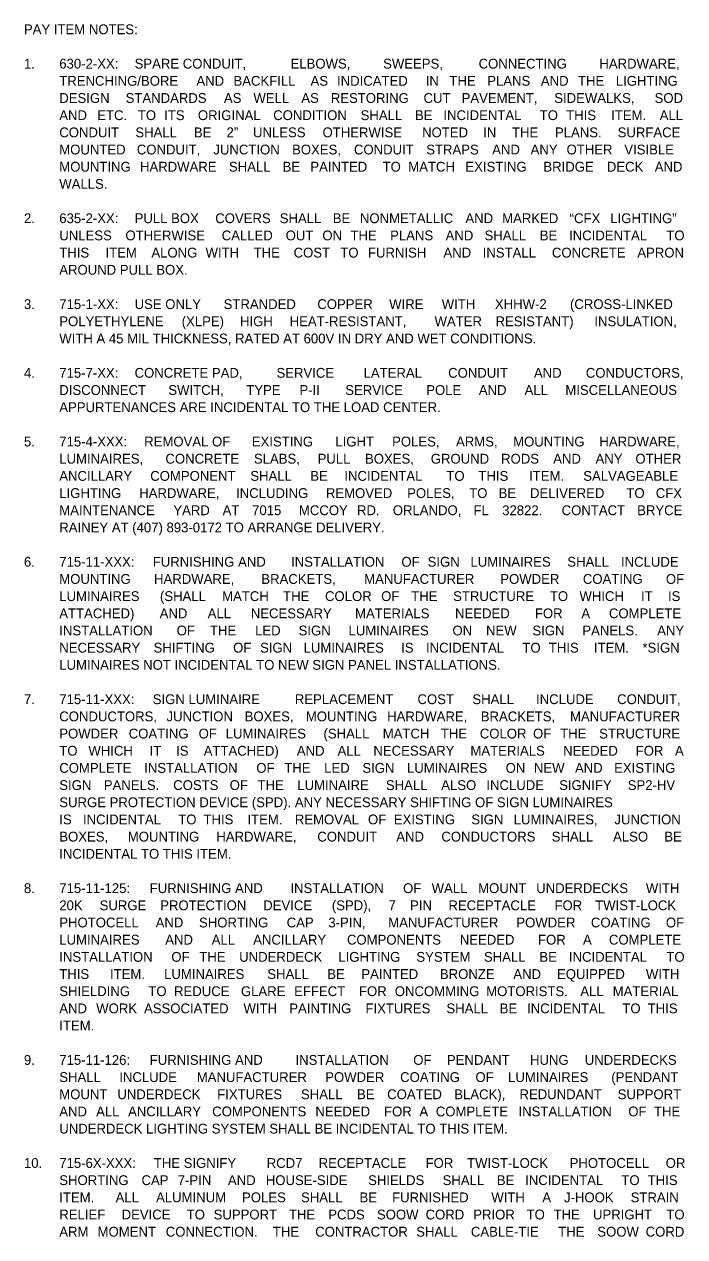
# Model space of a CAD drawing. Extents: x -55 to 2471539, y -90 to 3608906.
# Drawn here: x 27 to 498, y 2532 to 3397 of the extents above; entities that cross this region are included whole.
import ezdxf

# ---------------------------------------------------------------- set-up
doc = ezdxf.new("R2010")
doc.units = 0
doc.layers.add('XSCell', color=7, linetype='Continuous')

msp = doc.modelspace()

# ---------------------------------------------------------------- texts
at = {"layer": 'XSCell'}
for s, p in [('PAY ITEM NOTES:', (26.68, 3389.74)), ('630-2-XX:', (51.88, 3365.24)), (' SPARE CONDUIT, ', (103, 3365.24)), ('ELBOWS, ', (216.8, 3365.24)), ('SWEEPS, ', (282.82, 3365.24)), ('CONNECTING ', (350.92, 3365.24)), ('1.', (26.68, 3365.24)), ('HARDWARE, ', (437.06, 3365.24)), ('TRENCHING/BORE ', (51.88, 3352.99)), ('AND ', (149.66, 3352.99)), ('BACKFILL ', (176.11, 3352.99)), ('AS ', (231.06, 3352.99)), ('INDICATED ', (249.96, 3352.99)), ('IN ', (313.22, 3352.99)), ('THE ', (330.09, 3352.99)), ('PLANS ', (357.07, 3352.99)), ('AND ', (395.32, 3352.99)), ('THE ', (421.77, 3352.99)), ('LIGHTING ', (448.75, 3352.99)), ('DESIGN ', (51.88, 3340.74)), ('STANDARDS ', (99.2, 3340.74)), ('AS ', (169.29, 3340.74)), ('WELL ', (190.33, 3340.74)), ('AS ', (224.46, 3340.74)), ('RESTORING ', (245.49, 3340.74)), ('CUT ', (311.63, 3340.74)), ('PAVEMENT, ', (338.81, 3340.74)), ('SIDEWALKS, ', (404.84, 3340.74)), ('SOD ', (476.42, 3340.74)), ('AND ', (51.88, 3328.49)), ('ETC. ', (78.98, 3328.49)), ('TO ', (107.88, 3328.49)), ('ITS ', (126.69, 3328.49)), ('ORIGINAL ', (150.74, 3328.49)), ('CONDITION ', (204.43, 3328.49)), ('SHALL ', (266.79, 3328.49)), ('BE ', (305.52, 3328.49)), ('INCIDENTAL ', (325.8, 3328.49)), ('TO ', (394.52, 3328.49)), ('THIS ', (413.34, 3328.49)), ('ITEM. ', (445.46, 3328.49)), ('ALL ', (480.05, 3328.49)), ('CONDUIT ', (51.88, 3316.24)), ('SHALL ', (106.12, 3316.24)), ('BE ', (147.86, 3316.24)), ('2” ', (171.15, 3316.24)), ('UNLESS ', (190.04, 3316.24)), ('OTHERWISE ', (239.61, 3316.24)), ('NOTED ', (310.61, 3316.24)), ('IN ', (354.19, 3316.24)), ('THE ', (374.74, 3316.24)), ('PLANS. ', (405.39, 3316.24)), ('SURFACE ', (450.07, 3316.24)), ('MOUNTED ', (51.88, 3303.99)), ('CONDUIT, ', (107.18, 3303.99)), ('JUNCTION ', (161.77, 3303.99)), ('BOXES, ', (217.91, 3303.99)), ('CONDUIT ', (262.01, 3303.99)), ('STRAPS ', (313.55, 3303.99)), ('AND ', (360.6, 3303.99)), ('ANY ', (388, 3303.99)), ('OTHER ', (413.64, 3303.99)), ('VISIBLE ', (454.83, 3303.99)), ('MOUNTING ', (51.88, 3291.74)), ('HARDWARE ', (109.45, 3291.74)), ('SHALL ', (172.87, 3291.74)), ('BE ', (211.11, 3291.74)), ('PAINTED ', (230.91, 3291.74)), ('TO ', (282.44, 3291.74)), ('MATCH ', (300.77, 3291.74)), ('EXISTING ', (341.5, 3291.74)), ('BRIDGE ', (397.1, 3291.74)), ('DECK ', (442.4, 3291.74)), ('AND ', (476.52, 3291.74)), ('WALLS.', (51.88, 3279.49)), ('2.', (26.68, 3254.99)), ('635-2-XX:', (51.88, 3254.99)), (' PULL BOX ', (103, 3254.99)), ('COVERS ', (163.1, 3254.99)), ('SHALL ', (209.1, 3254.99)), ('BE ', (246.91, 3254.99)), ('NONMETALLIC ', (266.27, 3254.99)), ('AND ', (341.51, 3254.99)), ('MARKED ', (367.7, 3254.99)), ('“CFX ', (415.84, 3254.99)), ('LIGHTING” ', (444.82, 3254.99)), ('UNLESS ', (51.88, 3242.74)), ('OTHERWISE ', (99.08, 3242.74)), ('CALLED ', (167.72, 3242.74)), ('OUT ', (213.33, 3242.74)), ('ON ', (239.5, 3242.74)), ('THE ', (259.52, 3242.74)), ('PLANS ', (287.82, 3242.74)), ('AND ', (327.38, 3242.74)), ('SHALL ', (355.13, 3242.74)), ('BE ', (394.51, 3242.74)), ('INCIDENTAL ', (415.44, 3242.74)), ('TO ', (484.81, 3242.74)), ('THIS ', (51.88, 3230.49)), ('ITEM ', (84.87, 3230.49)), ('ALONG ', (117.57, 3230.49)), ('WITH ', (156.2, 3230.49)), ('THE ', (190.47, 3230.49)), ('COST ', (218.99, 3230.49)), ('TO ', (252.31, 3230.49)), ('FURNISH ', (272, 3230.49)), ('AND ', (325.85, 3230.49)), ('INSTALL ', (353.83, 3230.49)), ('CONCRETE ', (403.21, 3230.49)), ('APRON ', (464.1, 3230.49)), ('AROUND PULL BOX.', (51.88, 3218.24)), ('3.', (26.68, 3193.74)), ('715-1-XX:', (51.88, 3193.74)), (' USE ONLY ', (103, 3193.74)), ('STRANDED ', (169.1, 3193.74)), ('COPPER ', (235.88, 3193.74)), ('WIRE ', (287.14, 3193.74)), ('WITH ', (324.62, 3193.74)), ('XHHW-2 ', (362.53, 3193.74)), ('(CROSS-LINKED ', (416.09, 3193.74)), ('POLYETHYLENE ', (51.88, 3181.49)), ('(XLPE) ', (139.17, 3181.49)), ('HIGH ', (180.77, 3181.49)), ('HEAT-RESISTANT, ', (216.17, 3181.49)), ('WATER ', (319.51, 3181.49)), ('RESISTANT) ', (362.99, 3181.49)), ('INSULATION, ', (433.46, 3181.49)), ('WITH A 45 MIL THICKNESS, RATED AT 600V IN DRY AND WET CONDITIONS.', (51.88, 3169.24)), ('4.', (26.68, 3144.74)), ('715-7-XX:', (51.88, 3144.74)), (' CONCRETE PAD, ', (103, 3144.74)), ('SERVICE ', (206.77, 3144.74)), ('LATERAL ', (268.9, 3144.74)), ('CONDUIT ', (329.2, 3144.74)), ('AND ', (390.35, 3144.74)), ('CONDUCTORS, ', (427.37, 3144.74)), ('DISCONNECT ', (51.88, 3132.49)), ('SWITCH, ', (129.64, 3132.49)), ('TYPE ', (185.25, 3132.49)), ('P-II ', (223.15, 3132.49)), ('SERVICE ', (255.82, 3132.49)), ('POLE ', (313.56, 3132.49)), ('AND ', (351.06, 3132.49)), ('ALL ', (383.69, 3132.49)), ('MISCELLANEOUS ', (412.79, 3132.49)), ('APPURTENANCES ARE INCIDENTAL TO THE LOAD CENTER.', (51.88, 3120.24)), ('5.', (26.68, 3095.74)), ('715-4-XXX:', (51.88, 3095.74)), (' REMOVAL OF ', (109.83, 3095.74)), ('EXISTING ', (189.18, 3095.74)), ('LIGHT ', (248.74, 3095.74)), ('POLES, ', (289.22, 3095.74)), ('ARMS, ', (334.82, 3095.74)), ('MOUNTING ', (375.52, 3095.74)), ('HARDWARE, ', (437.06, 3095.74)), ('LUMINAIRES, ', (51.88, 3083.49)), ('CONCRETE ', (127.57, 3083.49)), ('SLABS, ', (190.68, 3083.49)), ('PULL ', (236.09, 3083.49)), ('BOXES, ', (269.91, 3083.49)), ('GROUND ', (316.81, 3083.49)), ('RODS ', (366.94, 3083.49)), ('AND ', (404.11, 3083.49)), ('ANY ', (434.3, 3083.49)), ('OTHER ', (462.73, 3083.49)), ('ANCILLARY ', (51.88, 3071.24)), ('COMPONENT ', (116.74, 3071.24)), ('SHALL ', (188.11, 3071.24)), ('INCIDENTAL ', (255.18, 3071.24)), ('TO ', (327.94, 3071.24)), ('THIS ', (350.78, 3071.24)), ('SALVAGEABLE ', (425.56, 3071.24)), ('BE ', (230.87, 3071.24)), ('ITEM. ', (386.93, 3071.24)), ('LIGHTING ', (51.88, 3058.99)), ('HARDWARE, ', (108.88, 3058.99)), ('INCLUDING ', (177.96, 3058.99)), ('REMOVED ', (242, 3058.99)), ('POLES, ', (299.96, 3058.99)), ('TO ', (344.21, 3058.99)), ('BE ', (365.15, 3058.99)), ('DELIVERED ', (387.56, 3058.99)), ('TO ', (456.32, 3058.99)), ('CFX ', (477.26, 3058.99)), ('MAINTENANCE ', (51.88, 3046.74)), ('YARD ', (133.22, 3046.74)), ('AT ', (168.37, 3046.74)), ('7015 ', (189.39, 3046.74)), ('MCCOY ', (222.77, 3046.74)), ('RD. ', (264.16, 3046.74)), ('ORLANDO, ', (289.72, 3046.74)), ('FL ', (347.22, 3046.74)), ('32822. ', (367.73, 3046.74)), ('CONTACT ', (410.15, 3046.74)), ('BRYCE ', (463.98, 3046.74)), ('RAINEY AT (407) 893-0172 TO ARRANGE DELIVERY.', (51.88, 3034.49)), ('6.', (26.68, 3009.99)), ('715-11-XXX:', (51.88, 3009.99)), (' FURNISHING AND ', (115.94, 3009.99)), ('INSTALLATION ', (217.19, 3009.99)), ('OF ', (295.86, 3009.99)), ('SIGN ', (314.55, 3009.99)), ('LUMINAIRES ', (345.11, 3009.99)), ('SHALL ', (414.2, 3009.99)), ('INCLUDE ', (452.46, 3009.99)), ('MOUNTING ', (51.88, 2997.74)), ('HARDWARE, ', (119.48, 2997.74)), ('BRACKETS, ', (195.97, 2997.74)), ('MANUFACTURER ', (269.31, 2997.74)), ('POWDER ', (366.37, 2997.74)), ('COATING ', (425.27, 2997.74)), ('OF ', (484.48, 2997.74)), ('LUMINAIRES ', (51.88, 2985.49)), ('(SHALL ', (123.68, 2985.49)), ('MATCH ', (168.01, 2985.49)), ('THE ', (211.48, 2985.49)), ('COLOR ', (241.38, 2985.49)), ('OF ', (281.43, 2985.49)), ('THE ', (302.84, 2985.49)), ('STRUCTURE ', (332.74, 2985.49)), ('TO ', (401.75, 2985.49)), ('WHICH ', (422.82, 2985.49)), ('IT ', (466.72, 2985.49)), ('IS ', (485.95, 2985.49)), ('ATTACHED) ', (51.88, 2973.24)), ('AND ', (123.47, 2973.24)), ('ALL ', (157.72, 2973.24)), ('NECESSARY ', (188.45, 2973.24)), ('MATERIALS ', (262.81, 2973.24)), ('NEEDED ', (334.12, 2973.24)), ('FOR ', (391.05, 2973.24)), ('A ', (424.22, 2973.24)), ('COMPLETE ', (443.85, 2973.24)), ('INSTALLATION ', (51.88, 2960.99)), ('OF ', (135.58, 2960.99)), ('THE ', (159.31, 2960.99)), ('LED ', (191.53, 2960.99)), ('SIGN ', (222.55, 2960.99)), ('LUMINAIRES ', (258.15, 2960.99)), ('ON ', (332.27, 2960.99)), ('NEW ', (356.22, 2960.99)), ('SIGN ', (389.3, 2960.99)), ('PANELS. ', (424.89, 2960.99)), ('ANY ', (478.27, 2960.99)), ('NECESSARY ', (51.88, 2948.74)), ('SHIFTING ', (119.12, 2948.74)), ('OF ', (175.87, 2948.74)), ('SIGN ', (195.05, 2948.74)), ('LUMINAIRES ', (226.1, 2948.74)), ('IS ', (295.69, 2948.74)), ('INCIDENTAL ', (313.39, 2948.74)), ('TO ', (382.15, 2948.74)), ('THIS ', (400.99, 2948.74)), ('ITEM. ', (433.14, 2948.74)), ('*SIGN ', (467.76, 2948.74)), ('LUMINAIRES NOT INCIDENTAL TO NEW SIGN PANEL INSTALLATIONS.', (51.88, 2936.49)), ('7.', (26.68, 2911.99)), ('715-11-XXX:', (51.88, 2911.99)), (' SIGN LUMINAIRE ', (115.94, 2911.99)), ('REPLACEMENT ', (219.87, 2911.99)), ('COST ', (307.32, 2911.99)), ('SHALL ', (346.46, 2911.99)), ('INCLUDE ', (391.87, 2911.99)), ('CONDUIT, ', (449.72, 2911.99)), ('CONDUCTORS, ', (51.88, 2899.74)), ('JUNCTION ', (128.38, 2899.74)), ('BOXES, ', (184.07, 2899.74)), ('MOUNTING ', (227.74, 2899.74)), ('HARDWARE, ', (285.65, 2899.74)), ('BRACKETS, ', (352.46, 2899.74)), ('MANUFACTURER ', (416.11, 2899.74)), ('POWDER ', (51.88, 2887.49)), ('COATING ', (101.4, 2887.49)), ('OF ', (151.24, 2887.49)), ('LUMINAIRES ', (170.57, 2887.49)), ('(SHALL ', (240.3, 2887.49)), ('MATCH ', (282.55, 2887.49)), ('THE ', (323.94, 2887.49)), ('COLOR ', (351.76, 2887.49)), ('OF ', (389.72, 2887.49)), ('THE ', (409.05, 2887.49)), ('STRUCTURE ', (436.87, 2887.49)), ('TO ', (51.88, 2875.24)), ('WHICH ', (72.65, 2875.24)), ('IT ', (116.27, 2875.24)), ('IS ', (135.21, 2875.24)), ('ATTACHED) ', (154.85, 2875.24)), ('AND ', (221.27, 2875.24)), ('ALL ', (250.34, 2875.24)), ('NECESSARY ', (275.89, 2875.24)), ('MATERIALS ', (345.07, 2875.24)), ('NEEDED ', (411.2, 2875.24)), ('FOR ', (462.95, 2875.24)), ('A ', (490.95, 2875.24)), ('COMPLETE ', (51.88, 2862.99)), ('INSTALLATION ', (112.45, 2862.99)), ('OF ', (192.38, 2862.99)), ('THE ', (212.33, 2862.99)), ('LED ', (240.77, 2862.99)), ('SIGN ', (268.01, 2862.99)), ('LUMINAIRES ', (299.83, 2862.99)), ('ON ', (370.17, 2862.99)), ('NEW ', (390.34, 2862.99)), ('AND ', (419.64, 2862.99)), ('EXISTING ', (447.54, 2862.99)), ('SIGN ', (51.88, 2850.74)), ('PANELS. ', (83.62, 2850.74)), ('COSTS ', (133.14, 2850.74)), ('OF ', (173.39, 2850.74)), ('THE ', (193.26, 2850.74)), ('LUMINAIRE ', (221.62, 2850.74)), ('SHALL ', (284.81, 2850.74)), ('ALSO ', (324.26, 2850.74)), ('INCLUDE ', (356.45, 2850.74)), ('SIGNIFY ', (408.34, 2850.74)), ('SP2-HV ', (457.26, 2850.74)), ('SURGE PROTECTION DEVICE (SPD). ANY NECESSARY SHIFTING OF SIGN LUMINAIRES ', (51.88, 2838.49)), ('IS ', (51.88, 2826.24)), ('INCIDENTAL ', (68.77, 2826.24)), ('TO ', (136.7, 2826.24)), ('THIS ', (154.73, 2826.24)), ('ITEM. ', (186.07, 2826.24)), ('REMOVAL ', (219.87, 2826.24)), ('OF ', (272.05, 2826.24)), ('EXISTING ', (290.42, 2826.24)), ('SIGN ', (345.72, 2826.24)), ('LUMINAIRES, ', (375.96, 2826.24)), ('JUNCTION ', (447.79, 2826.24)), ('BOXES, ', (51.88, 2813.99)), ('MOUNTING ', (100.75, 2813.99)), ('HARDWARE, ', (163.88, 2813.99)), ('CONDUIT ', (235.9, 2813.99)), ('AND ', (292.19, 2813.99)), ('CONDUCTORS ', (324.36, 2813.99)), ('SHALL ', (403.02, 2813.99)), ('ALSO ', (446.81, 2813.99)), ('BE ', (483.35, 2813.99)), ('INCIDENTAL TO THIS ITEM.', (51.88, 2801.74)), ('8.', (26.68, 2777.24)), ('715-11-125:', (51.88, 2777.24)), (' FURNISHING AND ', (113.78, 2777.24)), ('INSTALLATION ', (216.71, 2777.24)), ('OF ', (297.06, 2777.24)), ('WALL ', (317.43, 2777.24)), ('MOUNT ', (350.59, 2777.24)), ('UNDERDECKS ', (391.99, 2777.24)), ('WITH ', (470.23, 2777.24)), ('20K ', (51.88, 2764.99)), ('SURGE ', (80.64, 2764.99)), ('PROTECTION ', (123.89, 2764.99)), ('DEVICE ', (197.33, 2764.99)), ('(SPD), ', (246.25, 2764.99)), ('7 ', (286.69, 2764.99)), ('PIN ', (302.02, 2764.99)), ('RECEPTACLE ', (329.39, 2764.99)), ('FOR ', (405.04, 2764.99)), ('TWIST-LOCK ', (434.05, 2764.99)), ('PHOTOCELL ', (51.88, 2752.74)), ('AND ', (120.6, 2752.74)), ('SHORTING ', (151.52, 2752.74)), ('CAP ', (214.05, 2752.74)), ('3-PIN, ', (243.77, 2752.74)), ('MANUFACTURER ', (286.49, 2752.74)), ('POWDER ', (377.83, 2752.74)), ('COATING ', (431, 2752.74)), ('OF ', (484.48, 2752.74)), ('LUMINAIRES ', (51.88, 2740.49)), ('AND ', (127.45, 2740.49)), ('ALL ', (160.58, 2740.49)), ('ANCILLARY ', (190.18, 2740.49)), ('COMPONENTS ', (257.03, 2740.49)), ('NEEDED ', (337.48, 2740.49)), ('FOR ', (393.29, 2740.49)), ('A ', (425.34, 2740.49)), ('COMPLETE ', (443.85, 2740.49)), ('INSTALLATION ', (51.88, 2728.24)), ('OF ', (131.79, 2728.24)), ('THE ', (151.73, 2728.24)), ('UNDERDECK ', (180.16, 2728.24)), ('LIGHTING ', (250.89, 2728.24)), ('SYSTEM ', (306.55, 2728.24)), ('SHALL ', (354.73, 2728.24)), ('BE ', (394.24, 2728.24)), ('INCIDENTAL ', (415.3, 2728.24)), ('TO ', (484.81, 2728.24)), ('THIS ', (51.88, 2715.99)), ('ITEM. ', (88.03, 2715.99)), ('LUMINAIRES ', (126.65, 2715.99)), ('SHALL ', (200.23, 2715.99)), ('BE ', (242.98, 2715.99)), ('PAINTED ', (267.29, 2715.99)), ('BRONZE ', (323.33, 2715.99)), ('AND ', (375.7, 2715.99)), ('EQUIPPED ', (406.84, 2715.99)), ('WITH ', (470.23, 2715.99)), ('SHIELDING ', (51.88, 2703.74)), ('TO ', (115.39, 2703.74)), ('REDUCE ', (133.72, 2703.74)), ('GLARE ', (181.41, 2703.74)), ('EFFECT ', (219.38, 2703.74)), ('FOR ', (265.61, 2703.74)), ('ONCOMMING ', (291.16, 2703.74)), ('MOTORISTS. ', (356.32, 2703.74)), ('ALL ', (423.44, 2703.74)), ('MATERIAL ', (446.54, 2703.74)), ('AND ', (51.88, 2691.49)), ('WORK ', (78.23, 2691.49)), ('ASSOCIATED ', (112.3, 2691.49)), ('WITH ', (183.26, 2691.49)), ('PAINTING ', (215.9, 2691.49)), ('FIXTURES ', (270.22, 2691.49)), ('SHALL ', (327.97, 2691.49)), ('BE ', (365.95, 2691.49)), ('INCIDENTAL ', (385.47, 2691.49)), ('TO ', (453.45, 2691.49)), ('THIS ', (471.51, 2691.49)), ('ITEM. ', (51.88, 2679.24)), ('9.', (26.68, 2654.74)), ('715-11-126:', (51.88, 2654.74)), (' FURNISHING AND ', (113.78, 2654.74)), ('INSTALLATION ', (220.34, 2654.74)), ('OF ', (304.31, 2654.74)), ('PENDANT ', (328.31, 2654.74)), ('HUNG ', (387.57, 2654.74)), ('UNDERDECKS ', (426.6, 2654.74)), ('SHALL ', (51.88, 2642.49)), ('INCLUDE ', (94.68, 2642.49)), ('MANUFACTURER ', (149.93, 2642.49)), ('POWDER ', (241.52, 2642.49)), ('COATING ', (294.95, 2642.49)), ('OF ', (348.69, 2642.49)), ('LUMINAIRES ', (371.93, 2642.49)), ('(PENDANT ', (445.55, 2642.49)), ('BLACK), ', (333.58, 2630.24)), ('MOUNT ', (51.88, 2630.24)), ('UNDERDECK ', (93.3, 2630.24)), ('FIXTURES ', (164.49, 2630.24)), ('SHALL ', (224.24, 2630.24)), ('BE ', (264.21, 2630.24)), ('COATED ', (285.73, 2630.24)), ('REDUNDANT ', (380.06, 2630.24)), ('SUPPORT ', (450.12, 2630.24)), ('AND ', (51.88, 2617.99)), ('ALL ', (78.16, 2617.99)), ('ANCILLARY ', (100.92, 2617.99)), ('COMPONENTS ', (160.93, 2617.99)), ('NEEDED ', (234.54, 2617.99)), ('FOR ', (283.5, 2617.99)), ('A ', (308.71, 2617.99)), ('COMPLETE ', (320.38, 2617.99)), ('INSTALLATION ', (379.34, 2617.99)), ('OF ', (457.65, 2617.99)), ('THE ', (475.98, 2617.99)), ('UNDERDECK LIGHTING SYSTEM SHALL BE INCIDENTAL TO THIS ITEM.', (51.88, 2605.74)), ('10.', (26.68, 2581.24)), ('715-6X-XXX:', (51.88, 2581.24)), (' THE SIGNIFY ', (116.66, 2581.24)), ('RCD7 ', (199.82, 2581.24)), ('RECEPTACLE ', (236.86, 2581.24)), ('FOR ', (313.1, 2581.24)), ('TWIST-LOCK ', (342.7, 2581.24)), ('PHOTOCELL ', (415.84, 2581.24)), ('OR ', (484.31, 2581.24)), ('SHORTING ', (51.88, 2568.99)), ('CAP ', (110.52, 2568.99)), ('7-PIN ', (136.35, 2568.99)), ('AND ', (172.14, 2568.99)), ('HOUSE-SIDE ', (199.17, 2568.99)), ('SHIELDS ', (272.12, 2568.99)), ('SHALL ', (325.25, 2568.99)), ('BE ', (363.9, 2568.99)), ('INCIDENTAL ', (384.11, 2568.99)), ('TO ', (452.76, 2568.99)), ('THIS ', (471.51, 2568.99)), ('ITEM. ', (51.88, 2556.74)), (' ALL ', (89.44, 2556.74)), ('ALUMINUM ', (120.9, 2556.74)), ('POLES ', (182.23, 2556.74)), ('SHALL ', (224.27, 2556.74)), ('BE ', (265.97, 2556.74)), ('FURNISHED ', (289.22, 2556.74)), ('WITH ', (360, 2556.74)), ('A ', (396.37, 2556.74)), ('J-HOOK ', (411.83, 2556.74)), ('STRAIN ', (459.35, 2556.74)), ('RELIEF ', (51.88, 2544.49)), ('DEVICE ', (96.33, 2544.49)), ('TO ', (142.72, 2544.49)), ('SUPPORT ', (161.97, 2544.49)), ('THE ', (215.62, 2544.49)), ('PCDS ', (243.71, 2544.49)), ('SOOW ', (278.41, 2544.49)), ('CORD ', (313.1, 2544.49)), ('PRIOR ', (347.1, 2544.49)), ('TO ', (385.13, 2544.49)), ('THE ', (404.38, 2544.49)), ('UPRIGHT ', (432.47, 2544.49)), ('TO ', (484.81, 2544.49)), ('ARM ', (51.88, 2532.24)), ('MOMENT ', (79.21, 2532.24)), ('CONNECTION. ', (127.8, 2532.24)), (' THE ', (201.59, 2532.24)), ('CONTRACTOR ', (234.4, 2532.24)), ('SHALL ', (306.43, 2532.24)), ('CABLE-TIE ', (345.41, 2532.24)), ('THE ', (407.67, 2532.24)), ('SOOW ', (435.57, 2532.24)), ('CORD ', (470.06, 2532.24))]:
    msp.add_text(s, height=7, dxfattribs=at).set_placement(p)

doc.saveas('drawing.dxf')
